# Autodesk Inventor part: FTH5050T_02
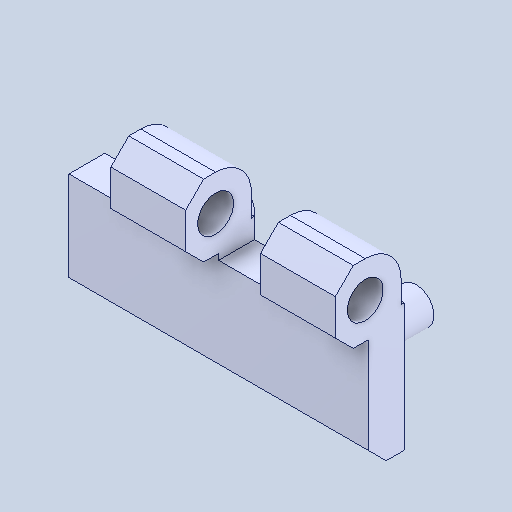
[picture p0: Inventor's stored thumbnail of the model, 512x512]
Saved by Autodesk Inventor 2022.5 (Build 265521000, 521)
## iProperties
Created: 2024-08
Part Number: FTH5050T_02
Material: 一般
Document SubType Name: Modeling
Designer: ImaoCorp
Density: 1 g/cm^3
Appearance: 既定
Author: ImaoCorp
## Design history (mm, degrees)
feature "FTH5050T_02"
node "ソリッド1"
